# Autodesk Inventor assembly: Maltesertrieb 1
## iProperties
Created: 2004-11
Part Number: Maltesertrieb 1
Document SubType Name: Assembly
Designer: PALME
Manufacturer: Standard
Standards Organization: Custom
Author: PALME
